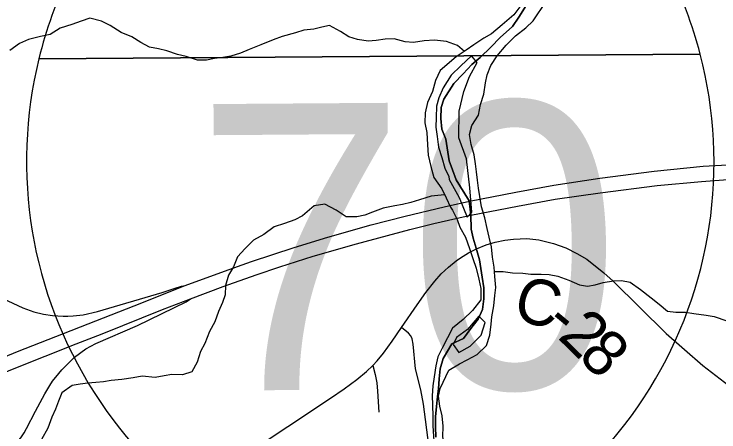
# Model space of a CAD drawing. Extents: x 114604 to 551442, y 316898 to 567001.
# Drawn here: x 133172 to 137786, y 392183 to 394917 of the extents above; entities that cross this region are included whole.
import ezdxf

# ---------------------------------------------------------------- set-up
doc = ezdxf.new("R2010")
doc.units = 0
for name, color, linetype in [('_CIVIL_CONSTRUCTION', 7, 'Continuous'), ('DV_X_County_Line', 7, 'Continuous'), ('GE_P_Alignment', 7, 'Continuous'), ('GE_P_Alignment_1000_Cardinal_Points', 7, 'Continuous'), ('GE_P_Alignment_500_Bearings', 7, 'Continuous'), ('GE_P_Alignment_500_Distances', 7, 'Continuous'), ('GE_P_Alignment_500_Stations', 7, 'Continuous'), ('PM_P_Cells', 7, 'Continuous'), ('PM_P_CL_Double_Solid', 7, 'Continuous'), ('PM_X_Stop_Line', 7, 'Continuous'), ('RS_Raster1', 7, 'Continuous')]:
    doc.layers.add(name, color=color, linetype=linetype)

msp = doc.modelspace()

# ---------------------------------------------------------------- linework, layer by layer
at = {"layer": '_CIVIL_CONSTRUCTION'}
for points in [[(132799.8, 393050), (132822, 393060.8), (132844.4, 393070.5), (132864.6, 393078.7), (132889, 393084.5), (132973.2, 393090), (132997.2, 393089.6), (133015.9, 393087.4), (133047.6, 393077.2), (133097.7, 393055.8), (133228.5, 392994.3), (133301.1, 392968.5), (133364.5, 392953.6), (133424.2, 392944.8), (133494, 392939), (133524.8, 392939.2), (133558.9, 392941.3), (133623.5, 392949.7), (133717.9, 392969.8), (134142.5, 393094.7), (134227.1, 393123.4), (134268, 393135.5), (134292.6, 393140.1)], [(133075.6, 392053.6), (133100.8, 392060.3), (133124.7, 392069), (133151.8, 392085.2), (133177.2, 392104.3), (133200.4, 392126.2), (133215.6, 392143.8), (133237.9, 392177.2), (133253.4, 392205), (133311.9, 392318.4), (133372.8, 392431.4), (133405.9, 392486.9), (133424, 392514), (133464, 392565.3), (133485.7, 392589.7), (133568, 392672), (133640.9, 392725.4), (133707.1, 392761.2), (133980.9, 392879.9), (134298.7, 393033.3), (134327.7, 393054)]]:
    msp.add_lwpolyline(points, dxfattribs=at)
at = {"layer": 'DV_X_County_Line'}
for points in [[(136018.5, 392586.7), (136086.6, 392628.6), (136138.7, 392654.6), (136202.7, 392688.5), (136264.8, 392748.5), (136287, 392816.6), (136295.1, 392886.6), (136299.2, 392936.7), (136313.3, 393006.7), (136319.5, 393074.8), (136325.6, 393126.8), (136319.7, 393198.9), (136313.8, 393261), (136304, 393325.1), (136296.1, 393393.2), (136282.2, 393457.2), (136268.3, 393513.3), (136254.5, 393583.4), (136232.6, 393655.5), (136220.7, 393723.6), (136212.8, 393777.7), (136204.9, 393829.7), (136199, 393883.8), (136193.1, 393935.9), (136183.3, 393995.9), (136163.4, 394064), (136153.5, 394128.1), (136167.6, 394188.2), (136211.8, 394256.2), (136225.9, 394324.2), (136246, 394392.3), (136258.2, 394466.3), (136268.3, 394518.4), (136292.4, 394580.4), (136334.5, 394644.4), (136392.6, 394714.4), (136454.7, 394774.4), (136520.8, 394826.4), (136570.9, 394872.4), (136655.1, 394998.4)], [(136495.1, 394982.6), (136443, 394912.6), (136366.9, 394846.6), (136296.8, 394788.6), (136246.7, 394758.7), (136180.7, 394714.7), (136130.6, 394680.7), (136066.5, 394636.8)], [(136066.5, 394636.8), (135962, 394547.1), (135931.5, 394481.2), (135910.9, 394411.2), (135878.4, 394339.3), (135863.8, 394271.3), (135861.3, 394205.2), (135874.8, 394141), (135878.2, 394060.9), (135881.6, 393992.7), (135901, 393918.4), (135920.5, 393848.2), (135971.9, 393773.6), (135999.4, 393713.3), (136028.9, 393653), (136042.6, 393633.7)], [(136021, 393834), (136084.7, 393715.8), (136138.5, 393587.6), (136168.5, 393621.6), (136154.8, 393779.8), (136133.2, 393970), (136083.5, 394106.2), (136085.8, 394282.4), (136116.1, 394410.5), (136152.2, 394508.5), (136202.4, 394600.5), (136166.5, 394644.6), (136096.4, 394578.7), (136032.3, 394516.7)], [(136032.3, 394516.7), (135981.1, 394434.8), (135952.6, 394368.8), (135936.2, 394314.9), (135935.6, 394240.7), (135933.1, 394176.7), (135940.6, 394116.5), (135950, 394046.3), (135971.5, 393978), (135990.9, 393907.7), (136018.5, 393853.4), (136021, 393834)], [(136042.6, 393633.7), (136072.5, 393573.6), (136090.3, 393521.5), (136126.2, 393457.4), (136154.1, 393383.3), (136173.9, 393317.2), (136197.8, 393253.1), (136213.7, 393183), (136227.6, 393121), (136227.4, 393046.9), (136173.3, 392976.9), (136111.2, 392918.9), (136041.1, 392860.9)], [(136255.1, 392898.7), (136213.2, 392940.8), (136139.1, 392852.8), (136067, 392800.8), (136046.9, 392754.8)], [(136046.9, 392754.8), (136082.8, 392702.7), (136156.8, 392742.7), (136229, 392814.6), (136255.1, 392898.7)], [(136041.1, 392860.9), (135975.7, 392735.8), (135945.2, 392673.9), (135932.8, 392613.9), (135922.2, 392543.8), (135913.7, 392483.8), (135909.2, 392419.7), (135910.8, 392359.6), (135912.2, 392283.4), (135913.7, 392223.3), (135917.1, 392155.2), (135922.7, 392093), (135932.1, 392022.8), (135943.6, 391954.6), (135971, 391882.3), (136006.4, 391809.9), (136035.9, 391745.6), (136038.9, 391737.7)], [(136037.4, 391998), (136026.1, 392018.1), (135988.6, 392086.5), (135979.1, 392150.7), (135981.7, 392220.8), (135974.2, 392287), (135958.7, 392351.2), (135951.2, 392415.4), (135961.6, 392467.4), (136018.5, 392586.7)]]:
    msp.add_lwpolyline(points, dxfattribs=at)
at = {"layer": 'GE_P_Alignment'}
for p, q in [((133334.6, 394624.5), (137663, 394655.6)), ((137663, 394655.6), (133334.6, 394624.5)), ((137663, 394655.6), (133334.6, 394624.5))]:
    msp.add_line(p, q, dxfattribs=at)
for centre, start, end in [((136066.3, 393954.4), 142.0805, 166.2182), ((134941.2, 393946.3), 14.605, 38.7427), ((136066.3, 393954.4), 166.2182, 258.8746), ((134941.2, 393946.3), 281.9486, 14.605)]:
    msp.add_arc(centre, 2812.7, start, end, dxfattribs=at)
at = {"layer": 'GE_P_Alignment_1000_Cardinal_Points'}
for points in [[(135797, 391780.1), (135816.7, 391808.2), (135842, 391854), (135861.6, 391901.9), (135875.7, 391950.6), (135890.2, 392048), (135887.2, 392096.7), (135851.3, 392364.4), (135833.9, 392456.9), (135798.6, 392596.3), (135785.4, 392755.8), (135777.2, 392791.7), (135768.3, 392810.8), (135753, 392829), (135708.1, 392866.3)], [(135520, 392617.3), (135536.3, 392557.3), (135546.1, 392503.6), (135550.9, 392448.4), (135559.1, 392311.1)]]:
    msp.add_lwpolyline(points, dxfattribs=at)
at = {"layer": 'GE_P_Alignment_500_Bearings'}
for points in [[(136198.7, 393381.6), (136261.1, 393407.3), (136321, 393424.6), (136384.1, 393437.5), (136441.9, 393444.8), (136527.5, 393449.3), (136606.5, 393440.2), (136702.5, 393416.6), (136784, 393388), (136855.9, 393349.6), (136921.7, 393313.7), (137032.8, 393223.5), (137093.8, 393168.1), (137439.9, 392826.5), (137679.4, 392617.5), (138049.7, 392333.1), (138153.1, 392237.2)], [(135520, 392617.3), (135548.7, 392647.7), (135590, 392698.6), (135646, 392776.3), (135708.1, 392866.3), (135810.5, 393014.9), (135867.3, 393094.7), (135925.7, 393169), (135968.5, 393216.2), (136014.6, 393260.9), (136064.9, 393301.5), (136093.3, 393321.6), (136146.8, 393354.9), (136198.7, 393381.6)], [(133248, 391086.8), (133280.7, 391104), (133330.3, 391133.7), (133445.9, 391209.3), (133854.5, 391479.5), (134125.7, 391661.3), (135242.4, 392403), (135332.5, 392464.9), (135416.7, 392526.3), (135479.4, 392578.3), (135520, 392617.3)]]:
    msp.add_lwpolyline(points, dxfattribs=at)
at = {"layer": 'GE_P_Alignment_500_Distances'}
for points in [[(136524.4, 394972.9), (136476.3, 394896.5), (136434.1, 394836.1), (136353.7, 394763.7), (136293.5, 394701.3), (136223.2, 394632.8), (136169, 394586.5), (136110.7, 394526.2), (136050.5, 394461.8), (135984.5, 394360.1), (135967.9, 394306), (135965.3, 394233.8), (135972.7, 394163.4), (135998.3, 394099), (136019.8, 393957.3), (136042.4, 393897.3), (136065, 393831.3), (136151.4, 393695.5), (136161.5, 393603.8), (136163.8, 393509), (136176.3, 393450.9), (136197.5, 393384.4), (136217.5, 393308.8), (136227.9, 393252.7), (136236.4, 393194.6), (136246.9, 393124.5), (136247.5, 393054.2), (136237.9, 392984), (136210.2, 392919.6), (136162.3, 392859), (136114.5, 392794.4), (136037.7, 392758.4), (135979.7, 392661.9), (135961.1, 392595.9), (135954.5, 392529.7), (135949.9, 392465.5), (135943.5, 392415.3), (135936.9, 392349.1), (135930.2, 392280.9), (135929.7, 392214.7), (135933.1, 392148.4)], [(135933.1, 392148.4), (135929.7, 392214.7), (135930.2, 392280.9), (135936.9, 392349.1), (135943.5, 392415.3), (135949.9, 392465.5), (135954.5, 392529.7), (135961.1, 392595.9), (135979.7, 392661.9), (136037.7, 392758.4), (136114.5, 392794.4), (136162.3, 392859), (136210.2, 392919.6), (136237.9, 392984), (136247.5, 393054.2), (136246.9, 393124.5), (136236.4, 393194.6), (136227.9, 393252.7), (136217.5, 393308.8), (136197.5, 393384.4), (136176.3, 393450.9), (136163.8, 393509), (136161.5, 393603.8), (136151.4, 393695.5), (136065, 393831.3), (136042.4, 393897.3), (136019.8, 393957.3), (135998.3, 394099), (135972.7, 394163.4), (135965.3, 394233.8), (135967.9, 394306), (135984.5, 394360.1), (136050.5, 394461.8), (136110.7, 394526.2), (136169, 394586.5), (136223.2, 394632.8), (136293.5, 394701.3), (136353.7, 394763.7), (136434.1, 394836.1), (136476.3, 394896.5), (136524.4, 394972.9)]]:
    msp.add_lwpolyline(points, dxfattribs=at)
at = {"layer": 'GE_P_Alignment_500_Stations'}
for points in [[(136152.6, 393692.7), (136456, 393751.5), (136704.4, 393796.4), (137005.6, 393843.5), (137362.5, 393889.1), (137683.3, 393920.6), (138001.5, 393940.1), (138354.3, 393961.6), (138715.6, 393965.6), (139127, 393957.4), (139510.7, 393939.3), (140025.2, 393906.9), (140576.2, 393869.9), (141713.1, 393802.3), (142520.9, 393753.9), (143174.3, 393709.5), (143530.3, 393693), (144456.2, 393631.2), (145464.4, 393572.1), (147608.3, 393440.2), (149153, 393339.8), (149953.9, 393295.9), (152348.2, 393147.7), (153524.4, 393072.4)], [(136162.7, 393601), (136466.2, 393659.8), (136714.6, 393704.7), (137008.9, 393747.1), (137382.4, 393795.7), (137671.3, 393821.4), (138045, 393850.5), (138634.1, 393867.2), (139070.4, 393863.5), (139516.6, 393841.7), (140133.3, 393803.6), (140459.3, 393785.9), (141766.3, 393705), (142497.6, 393658.8), (143184.5, 393617.9), (143668.3, 393589.4), (144466.4, 393539.5), (145395.2, 393480.9), (147031.7, 393380.1), (149163.2, 393248.1), (149978.7, 393198.5), (152362.4, 393050.1), (153534.5, 392980.7)], [(126118.5, 389909.1), (126544.9, 390079.1), (127399.6, 390416.1), (127642.6, 390514.4), (127739.3, 390552.6), (131456.5, 392020.2), (132904.6, 392591.9), (132948.5, 392609.2), (133012.6, 392634.5), (133195.1, 392708), (133958.8, 393007.6), (134292.6, 393140.1), (134549.1, 393235.5), (134725.6, 393297.5), (135006.1, 393389.4), (135225.5, 393457.5), (135509.7, 393537.2), (135732, 393595.3), (135987.2, 393656.3), (136152.6, 393692.7)], [(134327.7, 393054), (134540.6, 393134.2), (134757.2, 393210.7), (134912.5, 393262.6), (135130.8, 393332.1), (135413.8, 393413.9), (135761.8, 393506.2), (135920.7, 393545.8), (136111.9, 393590.6), (136162.7, 393601)], [(132907, 392489.1), (132926.3, 392496.9), (132969.8, 392514.6), (133172.5, 392597.1), (133577.6, 392758.2), (133749.8, 392825.1), (134144.3, 392983), (134327.7, 393054)]]:
    msp.add_lwpolyline(points, dxfattribs=at)
at = {"layer": 'PM_P_Cells'}
for points in [[(136001.8, 394736.5), (135923.8, 394746.5), (135855.9, 394742.5), (135785.9, 394730.6), (135731.9, 394734.6), (135660, 394754.6), (135602, 394752.6), (135542, 394744.7), (135490.1, 394740.7), (135420.1, 394750.7), (135362.2, 394768.8), (135308.2, 394802.8), (135236.3, 394842.9), (135186.3, 394830.9), (135134.3, 394818.9), (135068.4, 394810.9), (135014.4, 394794.9), (134926.4, 394770.9), (134868.4, 394748.9), (134786.5, 394714.9), (134710.5, 394684.8), (134654.5, 394660.8), (134590.5, 394640.8), (134538.6, 394632.8), (134484.6, 394626.8), (134432.6, 394614.8), (134372.6, 394614.9), (134298.7, 394638.9), (134242.7, 394653), (134172.8, 394677), (134116.8, 394689.1), (134058.9, 394701.1), (134002.9, 394731.2), (133943, 394767.2), (133873, 394797.3), (133801.1, 394841.4), (133745.2, 394869.5), (133667.2, 394889.5), (133611.2, 394871.5), (133551.2, 394849.5), (133473.3, 394825.5), (133407.3, 394783.4), (133345.3, 394769.4), (133267.4, 394751.4), (133207.4, 394725.4), (133143.4, 394679.4)], [(136119.3, 394673), (136075.1, 394711.6), (136001.8, 394736.5)], [(135990.3, 393733.2), (135901.2, 393725), (135825.2, 393701), (135769.3, 393683), (135715.3, 393671), (135665.3, 393661), (135587.3, 393647), (135517.4, 393621), (135467.4, 393601), (135415.4, 393591), (135345.4, 393591), (135279.5, 393633.1), (135205.6, 393673.2), (135135.6, 393661.2), (135059.6, 393597.1), (135009.6, 393571.1), (134941.6, 393547.1), (134873.7, 393525), (134807.7, 393475), (134739.7, 393437), (134683.7, 393382.9), (134633.7, 393328.9), (134607.7, 393262.7), (134575.6, 393208.7), (134555.6, 393140.6), (134553.6, 393080.5), (134535.5, 393028.4), (134509.5, 392970.3), (134485.5, 392902.3), (134451.5, 392840.2), (134421.4, 392762.1), (134393.4, 392708), (134371.4, 392637.9), (134335.4, 392575.8), (134275.4, 392555.8), (134205.4, 392557.8), (134153.5, 392549.8), (134095.5, 392537.8), (134009.5, 392547.9), (133951.6, 392535.9), (133877.6, 392525.9), (133807.6, 392517.9), (133757.7, 392509.9), (133707.7, 392505.9), (133655.7, 392501.9), (133603.8, 392493.9), (133551.8, 392486), (133483.8, 392437.9), (133463.8, 392383.8), (133443.7, 392331.8), (133419.7, 392279.7), (133393.7, 392207.6), (133351.7, 392133.5)], [(136316.5, 393232.3), (136373.1, 393232.7), (136435.1, 393224.4), (136501.1, 393222.2), (136555.1, 393214), (136621.1, 393215.7), (136675.1, 393213.5), (136731.1, 393201.3), (136803, 393175), (136872.9, 393144.7), (136924.8, 393136.5), (136974.9, 393144.3), (137027, 393160.1), (137095, 393171.9), (137149, 393173.7), (137205, 393161.4), (137272.8, 393115.1), (137342.6, 393060.8), (137394.4, 393018.5), (137448.2, 392972.3), (137504.2, 392966.1), (137566.2, 392965.8), (137622.2, 392957.6), (137702.1, 392947.3), (137754.1, 392937.1), (137927.9, 392878.3)]]:
    msp.add_lwpolyline(points, dxfattribs=at)
at = {"layer": 'RS_Raster1'}
for points in [[(136524.4, 394972.9), (136476.3, 394896.5), (136434.1, 394836.1), (136353.7, 394763.7), (136293.5, 394701.3), (136223.2, 394632.8), (136169, 394586.5), (136110.7, 394526.2), (136050.5, 394461.8), (135984.5, 394360.1), (135967.9, 394306), (135965.3, 394233.8), (135972.7, 394163.4), (135998.3, 394099), (136019.8, 393957.3), (136042.4, 393897.3), (136065, 393831.3), (136151.4, 393695.5), (136161.5, 393603.8), (136163.8, 393509), (136176.3, 393450.9), (136197.5, 393384.4), (136217.5, 393308.8), (136227.9, 393252.7), (136236.4, 393194.6), (136246.9, 393124.5), (136247.5, 393054.2), (136237.9, 392984), (136210.2, 392919.6), (136162.3, 392859), (136114.5, 392794.4), (136037.7, 392758.4), (135979.7, 392661.9), (135961.1, 392595.9), (135954.5, 392529.7), (135949.9, 392465.5), (135943.5, 392415.3), (135936.9, 392349.1), (135930.2, 392280.9), (135929.7, 392214.7), (135933.1, 392148.4)], [(135933.1, 392148.4), (135929.7, 392214.7), (135930.2, 392280.9), (135936.9, 392349.1), (135943.5, 392415.3), (135949.9, 392465.5), (135954.5, 392529.7), (135961.1, 392595.9), (135979.7, 392661.9), (136037.7, 392758.4), (136114.5, 392794.4), (136162.3, 392859), (136210.2, 392919.6), (136237.9, 392984), (136247.5, 393054.2), (136246.9, 393124.5), (136236.4, 393194.6), (136227.9, 393252.7), (136217.5, 393308.8), (136197.5, 393384.4), (136176.3, 393450.9), (136163.8, 393509), (136161.5, 393603.8), (136151.4, 393695.5), (136065, 393831.3), (136042.4, 393897.3), (136019.8, 393957.3), (135998.3, 394099), (135972.7, 394163.4), (135965.3, 394233.8), (135967.9, 394306), (135984.5, 394360.1), (136050.5, 394461.8), (136110.7, 394526.2), (136169, 394586.5), (136223.2, 394632.8), (136293.5, 394701.3), (136353.7, 394763.7), (136434.1, 394836.1), (136476.3, 394896.5), (136524.4, 394972.9)]]:
    msp.add_lwpolyline(points, dxfattribs=at)

# ---------------------------------------------------------------- texts
at = {"layer": 'GE_P_Alignment'}
msp.add_text('70', height=1875.1, rotation=0.4116, dxfattribs=at).set_placement((134362.2, 392452))
at = {"layer": 'PM_P_CL_Double_Solid'}
for s, rotation, p in [('C', 344.3033, (136425.4, 392926.5)), ('-', 320.2913, (136633.4, 392875.2)), ('2', 315.6361, (136723.4, 392800.8)), ('8', 315.4209, (136855.3, 392671.8))]:
    msp.add_text(s, height=300, rotation=rotation, dxfattribs=at).set_placement(p)
at = {"layer": 'PM_X_Stop_Line'}
for s, p in [('-', (135507.3, 393444.2)), ('.', (135507.3, 393444.2)), (',', (135507.3, 393444.2)), ('70', (135304.4, 393235.7))]:
    msp.add_text(s, height=1, rotation=0.4116, dxfattribs=at).set_placement(p)

doc.saveas('drawing.dxf')
